(* Logix 5000 project; controller EthernetIP_Demonstration vendor 1 type 14 code 106 rev 20.13; software revision 20.01 *)
// Project to demonstrate Dynacontrol v6 Ethernet/IP functionality
// by ITW Dynatec

TASK MainTask (continuous, watchdog 500 ms) : MainProgram

MODULES
   Local : vendor 1 type 14 code 106 (Compact 0, rev 20.13)
       : 1769-IQ16 (Compact 1, rev 1.1, Input RPI 20 ms)
       : 1769-OB16 (Compact 2, rev 2.1, Output RPI 20 ms)
      V6CONN : vendor 90 type 0 code 99 (Ethernet 192.168.65.252, rev 2.5, StandardDataDriven RPI 50 ms)
END_MODULES

TYPE UDT_V6_IN :   // Input Data from DynaControl V6
STRUCT
   SPARE1 : INT;   // Reserved
   SPARE2 : INT;   // Reserved
   GLOBAL_SYSSTAT_WATCHDOG : BOOL;   // Watchdog
   GLOBAL_SYSSTAT_READY : BOOL;   // System is Ready
   GLOBAL_SYSSTAT_FAULT : BOOL;   // System has a Fault
   GLOBAL_SYSSTAT_ALARM : BOOL;   // System is in Alarm State
   GLOBAL_SYSSTAT_ON : BOOL;   // System is On
   GLOBAL_SYSSTAT_STANDBY : BOOL;   // System is in Stand-By
   GLOBAL_SYSSTAT_LOW : BOOL;   // System has "Low Level"
   GLOBAL_SYSSTAT_PUMP1_ON : BOOL;   // Pump is On
   GLOBAL_SYSSTAT_PUMP2_ON : BOOL;   // Pump is On
   GLOBAL_SYSSTAT_PUMP3_ON : BOOL;   // Pump is On
   GLOBAL_SYSSTAT_PUMP4_ON : BOOL;   // Pump is On
   GLOBAL_SYSSTAT_PUMP5_ON : BOOL;   // Pump is On
   GLOBAL_SYSSTAT_PUMP6_ON : BOOL;   // Pump is On
   GLOBAL_SYSSTAT_PUMP7_ON : BOOL;   // Pump is On
   GLOBAL_SYSSTAT_PUMP8_ON : BOOL;   // Pump is On
   GLOBAL_SYSSTAT_PUMP9_ON : BOOL;   // Pump is On
   SPARE3 : INT;   // Reserved
   GLOBAL_LINESPEED : INT;   // 0..1000 = 0..100.0%
   ACT_PRESS1 : INT;   // 0..1000 = 0..100.0bar / 0..1000psi
   ACT_PRESS2 : INT;   // 0..1000 = 0..100.0bar / 0..1000psi
   ACT_PRESS3 : INT;   // 0..1000 = 0..100.0bar / 0..1000psi
   ACT_PRESS4 : INT;   // 0..1000 = 0..100.0bar / 0..1000psi
   ACT_PRESS5 : INT;   // 0..1000 = 0..100.0bar / 0..1000psi
   ACT_PRESS6 : INT;   // 0..1000 = 0..100.0bar / 0..1000psi
   ACT_PRESS7 : INT;   // 0..1000 = 0..100.0bar / 0..1000psi
   ACT_PRESS8 : INT;   // 0..1000 = 0..100.0bar / 0..1000psi
   ACT_PRESS9 : INT;   // 0..1000 = 0..100.0bar / 0..1000psi
   SPARE4 : INT;   // Reserved
   ACT_SPEED1 : INT;   // 0..1000 = 0..100.0rpm
   ACT_SPEED2 : INT;   // 0..1000 = 0..100.0rpm
   ACT_SPEED3 : INT;   // 0..1000 = 0..100.0rpm
   ACT_SPEED4 : INT;   // 0..1000 = 0..100.0rpm
   ACT_SPEED5 : INT;   // 0..1000 = 0..100.0rpm
   ACT_SPEED6 : INT;   // 0..1000 = 0..100.0rpm
   ACT_SPEED7 : INT;   // 0..1000 = 0..100.0rpm
   ACT_SPEED8 : INT;   // 0..1000 = 0..100.0rpm
   ACT_SPEED9 : INT;   // 0..1000 = 0..100.0rpm
   SPARE5 : INT;   // Reserved
   LAST_SUCC_WRITE_ID : INT;   // Last successful parameter Write UID
   SPARE6 : INT;   // Reserved
   SPARE7 : INT;   // Reserved
   READ_PARAM_BLK_TYPE1 : INT;   // Read Parameter Block Type #1
   READ_PARAM_BLK_UID : INT;   // Read Parameter Block UID
   READ_DATA : INT[16];   // Data from DynaControl V6
   READ_PARAM_BLK_TYPE2 : INT;   // Read Parameter Block Type #2
   SPARE8 : INT;   // Reserved
   SPARE9 : INT;   // Reserved
   SPARE10 : INT;   // Reserved
   SPARE11 : INT;   // Reserved
   SPARE12 : INT;   // Reserved
   SPARE13 : INT;   // Reserved
   SPARE14 : INT;   // Reserved
   SPARE15 : INT;   // Reserved
END_STRUCT
END_TYPE

TYPE UDT_V6_OUT :   // Output Paramters to DynaControl V6
STRUCT
   SPARE1 : INT;   // Reserved
   SPARE2 : INT;   // Reserved
   GLOBAL_SYSSET_ON : BOOL;   // System On
   GLOBAL_SYSSET_STANDBY : BOOL;   // Stand-By Mode
   GLOBAL_SYSSET_SPARE1 : BOOL;   // Reserved
   GLOBAL_SYSSET_ACK_ALM : BOOL;   // Reset Alarms
   GLOBAL_SYSSET_SPARE2 : BOOL;   // Reserved
   GLOBAL_SYSSET_WDOG : BOOL;   // Watchdog
   GLOBAL_SYSSET_SPARE3 : BOOL;   // Reserved
   GLOBAL_SYSSET_PUMP1_ON : BOOL;   // Start Pump
   GLOBAL_SYSSET_PUMP2_ON : BOOL;   // Start Pump
   GLOBAL_SYSSET_PUMP3_ON : BOOL;   // Start Pump
   GLOBAL_SYSSET_PUMP4_ON : BOOL;   // Start Pump
   GLOBAL_SYSSET_PUMP5_ON : BOOL;   // Start Pump
   GLOBAL_SYSSET_PUMP6_ON : BOOL;   // Start Pump
   GLOBAL_SYSSET_PUMP7_ON : BOOL;   // Start Pump
   GLOBAL_SYSSET_PUMP8_ON : BOOL;   // Start Pump
   GLOBAL_SYSSET_PUMP9_ON : BOOL;   // Start Pump
   GLOBAL_SYSCTRL_BUSCTRL : BOOL;   // Bus takes Control
   GLOBAL_SYSCTRL_BUSLS : BOOL;   // Global Line Speed supplied via Bus
   GLOBAL_SYSCTRL_SPARE1 : BOOL;   // Reserved
   GLOBAL_SYSCTRL_SPARE2 : BOOL;   // Reserved
   GLOBAL_SYSCTRL_SPARE3 : BOOL;   // Reserved
   GLOBAL_SYSCTRL_SPARE4 : BOOL;   // Reserved
   GLOBAL_SYSCTRL_SPARE5 : BOOL;   // Reserved
   GLOBAL_SYSCTRL_SPARE6 : BOOL;   // Reserved
   GLOBAL_SYSCTRL_IMPERIAL : BOOL;   // Unit uses Imperial Units (°F/psi)
   GLOBAL_SYSCTRL_SPARE7 : BOOL;   // Reserved
   GLOBAL_SYSCTRL_SPARE8 : BOOL;   // Reserved
   GLOBAL_SYSCTRL_SPARE9 : BOOL;   // Reserved
   GLOBAL_SYSCTRL_SPARE10 : BOOL;   // Reserved
   GLOBAL_SYSCTRL_SPARE11 : BOOL;   // Reserved
   GLOBAL_SYSCTRL_SPARE12 : BOOL;   // Reserved
   GLOBAL_SYSCTRL_SPARE13 : BOOL;   // Reserved
   GLOBAL_LS : INT;   // Global Line Speed
   MOTOR1_SP : INT;   // Motor SP (0..1000 = 0..100.0%, BIT15 = AUTO)
   MOTOR2_SP : INT;   // Motor SP (0..1000 = 0..100.0%, BIT15 = AUTO)
   MOTOR3_SP : INT;   // Motor SP (0..1000 = 0..100.0%, BIT15 = AUTO)
   MOTOR4_SP : INT;   // Motor SP (0..1000 = 0..100.0%, BIT15 = AUTO)
   MOTOR5_SP : INT;   // Motor SP (0..1000 = 0..100.0%, BIT15 = AUTO)
   MOTOR6_SP : INT;   // Motor SP (0..1000 = 0..100.0%, BIT15 = AUTO)
   MOTOR7_SP : INT;   // Motor SP (0..1000 = 0..100.0%, BIT15 = AUTO)
   MOTOR8_SP : INT;   // Motor SP (0..1000 = 0..100.0%, BIT15 = AUTO)
   MOTOR9_SP : INT;   // Motor SP (0..1000 = 0..100.0%, BIT15 = AUTO)
   RD_BLK_TYPE : INT;   // Parameter Read Block Type
   RD_BLK_UID : INT;   // Parameter Read Block UID
   SPARE3 : INT;   // Reserved
   SPARE4 : INT;   // Reserved
   WR_BLK_TYPE1 : INT;   // Parameter Write Block Type #1
   WR_BLK_UID : INT;   // Parameter Write Block UID
   SPARE5 : INT;   // Reserved
   SPARE6 : INT;   // Reserved
   DATA : INT[16];   // Data to DynaControl V6
   WR_BLK_TYPE2 : INT;   // Parameter Write Block Type #2
   SPARE7 : INT;   // Reserved
   SPARE8 : INT;   // Reserved
   SPARE9 : INT;   // Reserved
   SPARE10 : INT;   // Reserved
   SPARE11 : INT;   // Reserved
   SPARE12 : INT;   // Reserved
   SPARE13 : INT;   // Reserved
   SPARE14 : INT;   // Reserved
   SPARE15 : INT;   // Reserved
   SPARE16 : INT;   // Reserved
   SPARE17 : INT;   // Reserved
   SPARE18 : INT;   // Reserved
   SPARE19 : INT;   // Reserved
   SPARE20 : INT;   // Reserved
   SPARE21 : INT;   // Reserved
   SPARE22 : INT;   // Reserved
   SPARE23 : INT;   // Reserved
   SPARE24 : INT;   // Reserved
   SPARE25 : INT;   // Reserved
   SPARE26 : INT;   // Reserved
   SPARE27 : INT;   // Reserved
   SPARE28 : INT;   // Reserved
END_STRUCT
END_TYPE

VAR_GLOBAL   (* controller tags *)
   ACT_TEMPS17_32 : INT[16] := ([0] := 32, [1] := 32, [2] := 32, [3] := 32, [4] := 32, [5] := 32, [6] := 32, [7] := 32, [8] := 32, [9] := 32, [10] := 32, [11] := 32, [12] := 32, [13] := 32, [14] := 32, [15] := 32);   // Actual Temperatures Zones 17..32
   ACT_TEMPS1_16 : INT[16] := ([0] := 259, [1] := 259, [2] := 259, [3] := 256, [4] := 259, [5] := 260, [6] := 261, [7] := 259, [8] := 263, [9] := 265, [10] := 258, [11] := 261, [12] := 264, [13] := 264, [14] := 259, [15] := 259);   // Actual Temperatures Zones 1..16
   DyCo6_IN : UDT_V6_IN := (GLOBAL_SYSSTAT_WATCHDOG := 1, GLOBAL_SYSSTAT_READY := 1, GLOBAL_SYSSTAT_ON := 1, GLOBAL_SYSSTAT_PUMP1_ON := 1, GLOBAL_LINESPEED := 3, ACT_PRESS1 := -32768, ACT_PRESS2 := -32768, ACT_PRESS3 := -32768, ACT_PRESS4 := -32768, ACT_PRESS5 := -32768, ACT_PRESS6 := -32768, ACT_PRESS7 := -32768, ACT_PRESS8 := -32768, ACT_PRESS9 := -32768, ACT_SPEED1 := 450, READ_PARAM_BLK_TYPE1 := 24, READ_DATA[0] := 212, READ_DATA[1] := 212, READ_DATA[2] := 212, READ_DATA[3] := 212, READ_DATA[4] := 212, READ_DATA[5] := 212, READ_DATA[6] := 212, READ_DATA[7] := 212, READ_DATA[8] := 212, READ_DATA[9] := 212, READ_DATA[10] := 212, READ_DATA[11] := 212, READ_DATA[12] := 212, READ_DATA[13] := 212, READ_DATA[14] := 212, READ_DATA[15] := 212, READ_PARAM_BLK_TYPE2 := 24);
   DyCo6_OUT : UDT_V6_OUT := (GLOBAL_SYSSET_ON := 1, GLOBAL_SYSSET_WDOG := 1, GLOBAL_SYSSET_PUMP1_ON := 1, GLOBAL_SYSCTRL_BUSCTRL := 1, GLOBAL_SYSCTRL_IMPERIAL := 1, MOTOR1_SP := 500, DATA[0] := 250, DATA[1] := 251, DATA[2] := 252, DATA[3] := 253, DATA[4] := 254, DATA[5] := 255, DATA[6] := 256, DATA[7] := 257, DATA[8] := 258, DATA[9] := 259, DATA[10] := 260, DATA[11] := 261, DATA[12] := 262, DATA[13] := 263, DATA[14] := 264, DATA[15] := 265);
   SET_TEMPS17_32 : INT[16] := ([0] := 266, [1] := 267, [2] := 268, [3] := 269, [4] := 270, [5] := 271, [6] := 272, [7] := 273, [8] := 274, [9] := 275, [10] := 276, [11] := 277, [12] := 278, [13] := 279, [14] := 280, [15] := 281);   // Set Points Temperatures Zones 17..32
   SET_TEMPS1_16 : INT[16] := ([0] := 250, [1] := 251, [2] := 252, [3] := 253, [4] := 254, [5] := 255, [6] := 256, [7] := 257, [8] := 258, [9] := 259, [10] := 260, [11] := 261, [12] := 262, [13] := 263, [14] := 264, [15] := 265);   // Set Points Temperatures Zones 1..16
   SPR_TEMP17_32 : INT[16] := ([0] := 212, [1] := 212, [2] := 212, [3] := 212, [4] := 212, [5] := 212, [6] := 212, [7] := 212, [8] := 212, [9] := 212, [10] := 212, [11] := 212, [12] := 212, [13] := 212, [14] := 212, [15] := 212);   // Set Points (Read Back)
   SPR_TEMPS1_16 : INT[16] := ([0] := 250, [1] := 251, [2] := 252, [3] := 253, [4] := 254, [5] := 255, [6] := 256, [7] := 257, [8] := 258, [9] := 259, [10] := 260, [11] := 261, [12] := 262, [13] := 263, [14] := 264, [15] := 265);   // Set Points (Read Back)
   WRITE_UID : INT := 135;   // Unique Write ID
END_VAR

PROGRAM MainProgram   (* main routine MainRoutine *)
VAR
   CUST_Motor1On : BOOL := 1;
   CUST_SystemOn : BOOL := 1;
   CUST_SystemStandBy : BOOL;
   CUST_UpdateZ17_32 : BOOL;   // Update Temperature SPs Zone 17..32 (Request)
   CUST_UpdateZ1_16 : BOOL;   // Update Temperature SPs Zone 1..16 (Request)
   onsUpdateZ17_32 : BOOL;
   onsUpdateZ1_16 : BOOL;
END_VAR

ROUTINE GetDataFromV6   (* ladder *)
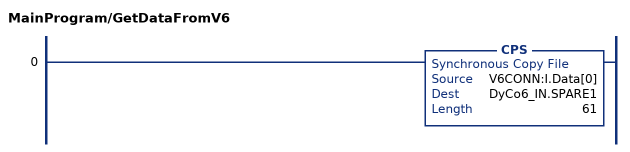
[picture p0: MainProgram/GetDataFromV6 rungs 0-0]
   0: CPS(V6CONN:I.Data[0],DyCo6_IN.SPARE1,61);
END_ROUTINE

ROUTINE Handle_V6   (* ladder *)
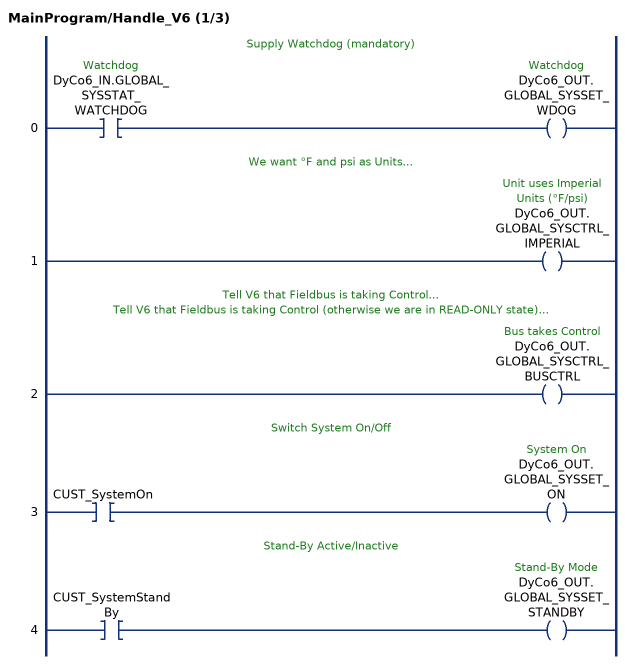
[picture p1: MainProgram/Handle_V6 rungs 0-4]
   // Supply Watchdog (mandatory)
   0: XIC(DyCo6_IN.GLOBAL_SYSSTAT_WATCHDOG)OTE(DyCo6_OUT.GLOBAL_SYSSET_WDOG);
   // We want °F and psi as Units...
   1: OTE(DyCo6_OUT.GLOBAL_SYSCTRL_IMPERIAL);
   // Tell V6 that Fieldbus is taking Control...
   // Tell V6 that Fieldbus is taking Control (otherwise we are in READ-ONLY state)...
   2: OTE(DyCo6_OUT.GLOBAL_SYSCTRL_BUSCTRL);
   // Switch System On/Off
   3: XIC(CUST_SystemOn)OTE(DyCo6_OUT.GLOBAL_SYSSET_ON);
   // Stand-By Active/Inactive
   4: XIC(CUST_SystemStandBy)OTE(DyCo6_OUT.GLOBAL_SYSSET_STANDBY);
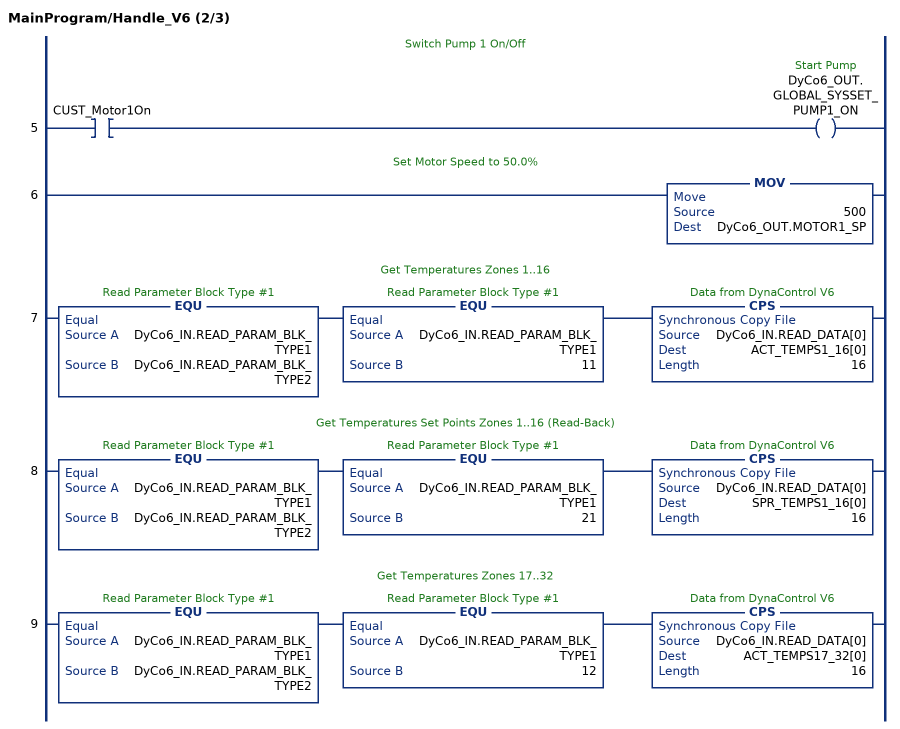
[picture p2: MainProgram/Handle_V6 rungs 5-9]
   // Switch Pump 1 On/Off
   5: XIC(CUST_Motor1On)OTE(DyCo6_OUT.GLOBAL_SYSSET_PUMP1_ON);
   // Set Motor Speed to 50.0%
   6: MOV(500,DyCo6_OUT.MOTOR1_SP);
   // Get Temperatures Zones 1..16
   7: EQU(DyCo6_IN.READ_PARAM_BLK_TYPE1,DyCo6_IN.READ_PARAM_BLK_TYPE2)EQU(DyCo6_IN.READ_PARAM_BLK_TYPE1,11)CPS(DyCo6_IN.READ_DATA[0],ACT_TEMPS1_16[0],16);
   // Get Temperatures Set Points Zones 1..16 (Read-Back)
   8: EQU(DyCo6_IN.READ_PARAM_BLK_TYPE1,DyCo6_IN.READ_PARAM_BLK_TYPE2)EQU(DyCo6_IN.READ_PARAM_BLK_TYPE1,21)CPS(DyCo6_IN.READ_DATA[0],SPR_TEMPS1_16[0],16);
   // Get Temperatures Zones 17..32
   9: EQU(DyCo6_IN.READ_PARAM_BLK_TYPE1,DyCo6_IN.READ_PARAM_BLK_TYPE2)EQU(DyCo6_IN.READ_PARAM_BLK_TYPE1,12)CPS(DyCo6_IN.READ_DATA[0],ACT_TEMPS17_32[0],16);
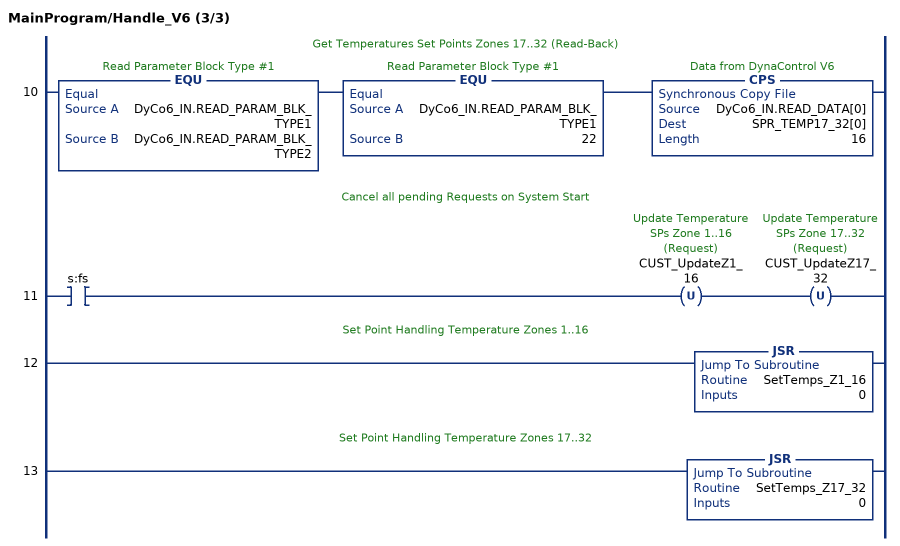
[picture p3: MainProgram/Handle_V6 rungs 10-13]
   // Get Temperatures Set Points Zones 17..32 (Read-Back)
   10: EQU(DyCo6_IN.READ_PARAM_BLK_TYPE1,DyCo6_IN.READ_PARAM_BLK_TYPE2)EQU(DyCo6_IN.READ_PARAM_BLK_TYPE1,22)CPS(DyCo6_IN.READ_DATA[0],SPR_TEMP17_32[0],16);
   // Cancel all pending Requests on System Start
   11: XIC(s:fs)OTU(CUST_UpdateZ1_16)OTU(CUST_UpdateZ17_32);
   // Set Point Handling Temperature Zones 1..16
   12: JSR(SetTemps_Z1_16,0);
   // Set Point Handling Temperature Zones 17..32
   13: JSR(SetTemps_Z17_32,0);
END_ROUTINE

ROUTINE MainRoutine   (* ladder *)
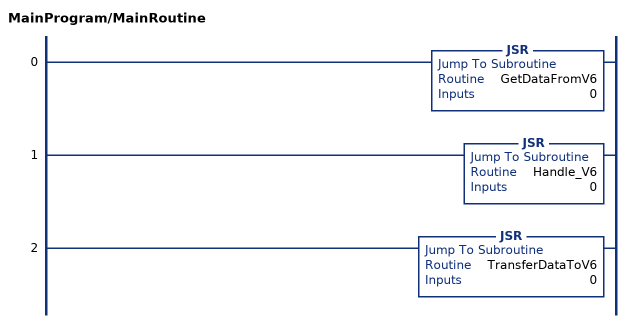
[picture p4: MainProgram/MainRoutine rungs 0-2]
   0: JSR(GetDataFromV6,0);
   1: JSR(Handle_V6,0);
   2: JSR(TransferDataToV6,0);
END_ROUTINE

ROUTINE SetTemps_Z17_32   (* ladder *)
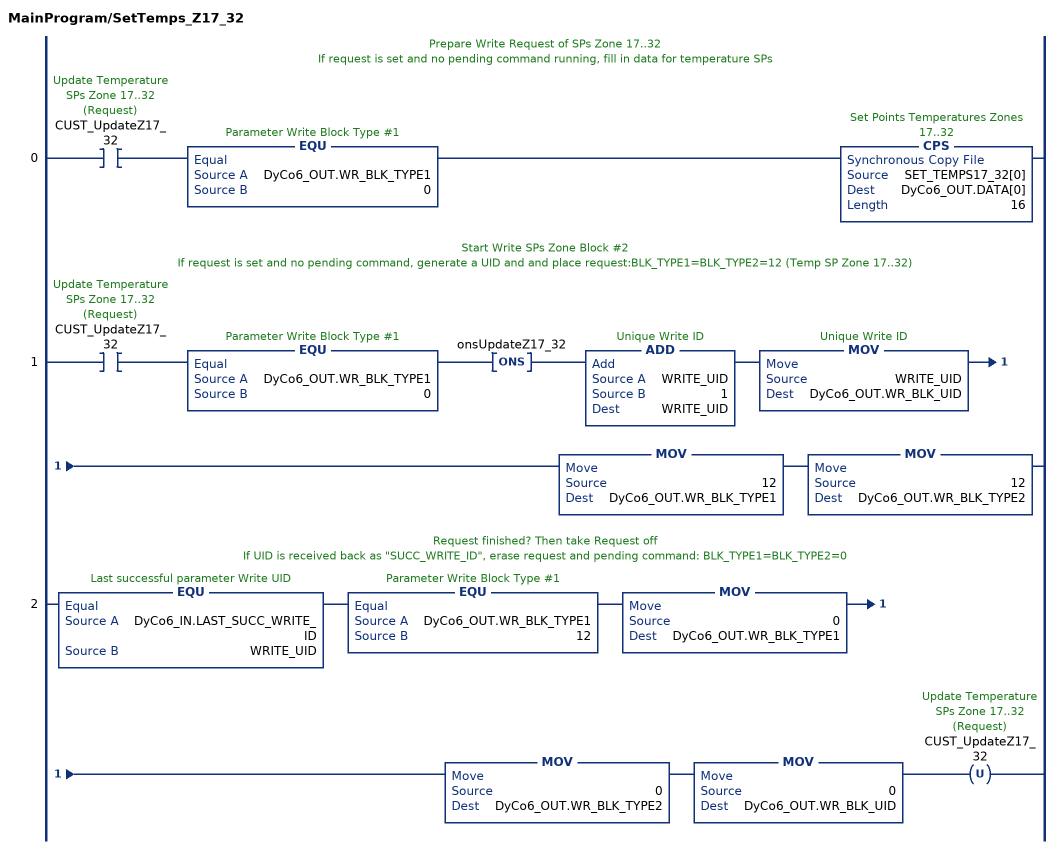
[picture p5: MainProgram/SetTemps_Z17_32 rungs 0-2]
   // Prepare Write Request of SPs Zone 17..32
   // If request is set and no pending command running, fill in data for temperature SPs
   0: XIC(CUST_UpdateZ17_32)EQU(DyCo6_OUT.WR_BLK_TYPE1,0)CPS(SET_TEMPS17_32[0],DyCo6_OUT.DATA[0],16);
   // Start Write SPs Zone Block #2
   // If request is set and no pending command, generate a UID and and place request:BLK_TYPE1=BLK_TYPE2=12 (Temp SP Zone 17..32)
   1: XIC(CUST_UpdateZ17_32)EQU(DyCo6_OUT.WR_BLK_TYPE1,0)ONS(onsUpdateZ17_32)ADD(WRITE_UID,1,WRITE_UID)MOV(WRITE_UID,DyCo6_OUT.WR_BLK_UID)MOV(12,DyCo6_OUT.WR_BLK_TYPE1)MOV(12,DyCo6_OUT.WR_BLK_TYPE2);
   // Request finished? Then take Request off
   // If UID is received back as "SUCC_WRITE_ID", erase request and pending command: BLK_TYPE1=BLK_TYPE2=0
   2: EQU(DyCo6_IN.LAST_SUCC_WRITE_ID,WRITE_UID)EQU(DyCo6_OUT.WR_BLK_TYPE1,12)MOV(0,DyCo6_OUT.WR_BLK_TYPE1)MOV(0,DyCo6_OUT.WR_BLK_TYPE2)MOV(0,DyCo6_OUT.WR_BLK_UID)OTU(CUST_UpdateZ17_32);
END_ROUTINE

ROUTINE SetTemps_Z1_16   (* ladder *)
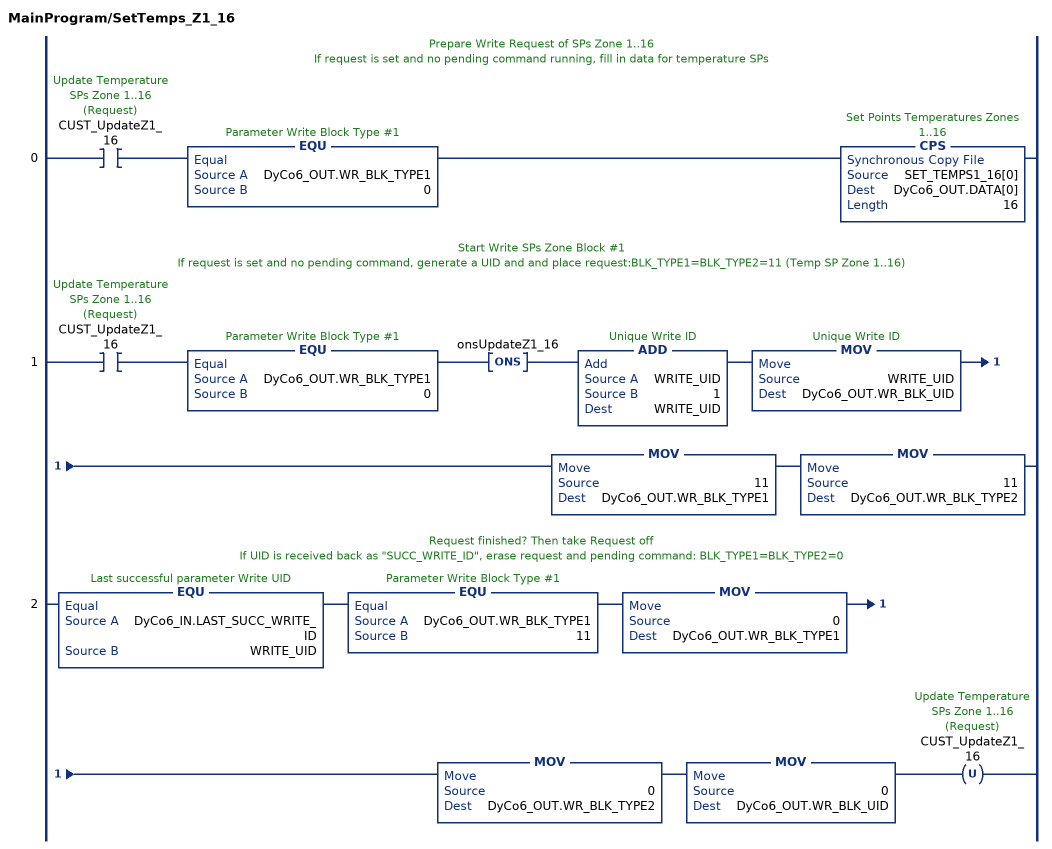
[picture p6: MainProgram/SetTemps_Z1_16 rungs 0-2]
   // Prepare Write Request of SPs Zone 1..16
   // If request is set and no pending command running, fill in data for temperature SPs
   0: XIC(CUST_UpdateZ1_16)EQU(DyCo6_OUT.WR_BLK_TYPE1,0)CPS(SET_TEMPS1_16[0],DyCo6_OUT.DATA[0],16);
   // Start Write SPs Zone Block #1
   // If request is set and no pending command, generate a UID and and place request:BLK_TYPE1=BLK_TYPE2=11 (Temp SP Zone 1..16)
   1: XIC(CUST_UpdateZ1_16)EQU(DyCo6_OUT.WR_BLK_TYPE1,0)ONS(onsUpdateZ1_16)ADD(WRITE_UID,1,WRITE_UID)MOV(WRITE_UID,DyCo6_OUT.WR_BLK_UID)MOV(11,DyCo6_OUT.WR_BLK_TYPE1)MOV(11,DyCo6_OUT.WR_BLK_TYPE2);
   // Request finished? Then take Request off
   // If UID is received back as "SUCC_WRITE_ID", erase request and pending command: BLK_TYPE1=BLK_TYPE2=0
   2: EQU(DyCo6_IN.LAST_SUCC_WRITE_ID,WRITE_UID)EQU(DyCo6_OUT.WR_BLK_TYPE1,11)MOV(0,DyCo6_OUT.WR_BLK_TYPE1)MOV(0,DyCo6_OUT.WR_BLK_TYPE2)MOV(0,DyCo6_OUT.WR_BLK_UID)OTU(CUST_UpdateZ1_16);
END_ROUTINE

ROUTINE TransferDataToV6   (* ladder *)
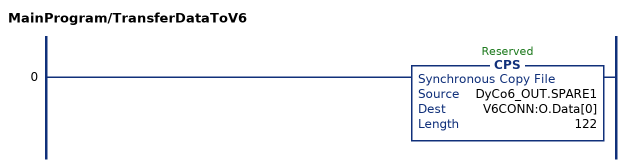
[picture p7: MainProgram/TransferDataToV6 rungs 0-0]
   0: CPS(DyCo6_OUT.SPARE1,V6CONN:O.Data[0],122);
END_ROUTINE
END_PROGRAM
